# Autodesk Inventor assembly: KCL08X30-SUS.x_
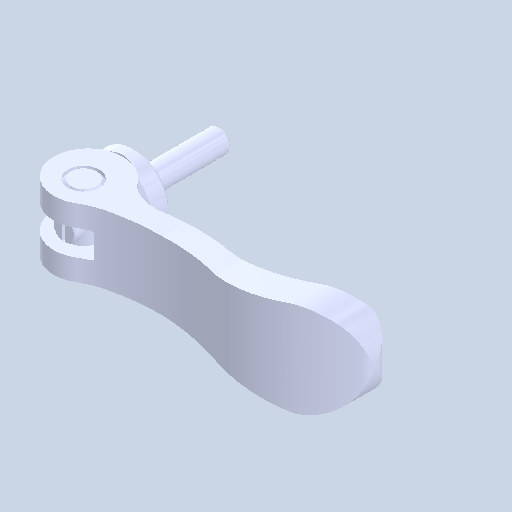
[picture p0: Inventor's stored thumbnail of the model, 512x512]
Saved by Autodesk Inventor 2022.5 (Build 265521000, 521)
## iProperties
Created: 2024-08
Part Number: KCL08X30-SUS.x_
Document SubType Name: Assembly
Designer: ImaoCorp
Author: ImaoCorp
Sending System: SOLIDWORKS 2022-2022290
MC: AMD64
MC_MODEL: Intel64 Family 6 Model 60 Stepping 3, GenuineIntel
OS: Windows_NT
FRU: Parasolid Version 33.1, build 260,  4-25-2022
FORMAT: text
GUISE: transmit
KEY: FILEKCL08X30-SUS.x_t
DATE: Thu Aug 29 10:50:31 2024
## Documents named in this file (5)
- Y:\5.更新分\2024年対応\1001_KCL\データ\kcl08x30-sus\KCL08X30-SUS.x_.iam
- Y:\5.更新分\2024年対応\1001_KCL\データ\kcl08x30-sus\KCL08X30-SUS_01.ipt
- Y:\5.更新分\2024年対応\1001_KCL\データ\kcl08x30-sus\KCL08X30-SUS_02.ipt
- Y:\5.更新分\2024年対応\1001_KCL\データ\kcl08x30-sus\KCL08X30-SUS_03.ipt
- Y:\5.更新分\2024年対応\1001_KCL\データ\kcl08x30-sus\KCL08X30-SUS_04.ipt
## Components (4 placed, 4 different names)
1. KCL08X30-SUS_01
2. KCL08X30-SUS_02
3. KCL08X30-SUS_03
4. KCL08X30-SUS_04
